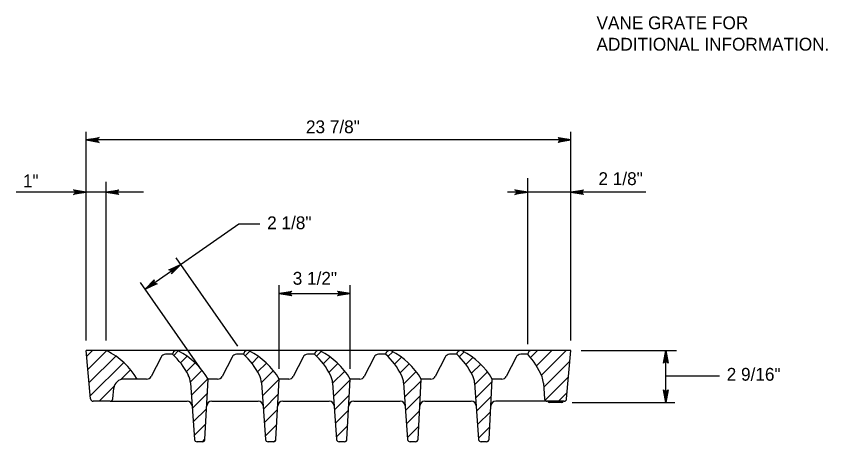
# Model space of a CAD drawing. Extents: x 2087776 to 2104538, y 970919 to 982612.
# Drawn here: x 2097624 to 2098246, y 977730 to 978057 of the extents above; entities that cross this region are included whole.
import ezdxf

# ---------------------------------------------------------------- set-up
doc = ezdxf.new("R2010")
doc.units = 0
doc.layers.add('1', color=7, linetype='Continuous')

msp = doc.modelspace()

# ---------------------------------------------------------------- linework, layer by layer
at = {"layer": '1'}
for p, q in [((2097677.36, 977807.97), (2097677.36, 977967.86)), ((2098048.69, 977807.97), (2098048.69, 977967.86)), ((2098048.69, 977961.64), (2097677.36, 977961.64)), ((2098048.69, 977961.64), (2098048.69, 977961.64)), ((2098015.64, 977805.05), (2098015.64, 977932.25)), ((2097692.61, 977807.97), (2097692.61, 977929.44)), ((2097721.26, 977921.64), (2097623.65, 977921.64)), ((2098106.11, 977921.64), (2098000.05, 977921.64)), ((2098048.69, 977807.97), (2098048.69, 977901.23)), ((2097722.51, 977847.21), (2097794.12, 977897.24)), ((2097794.12, 977897.24), (2097810.3, 977897.24)), ((2097677.36, 977807.97), (2097677.36, 977873.52)), ((2097793.44, 977803.65), (2097746.17, 977871.32)), ((2097749.73, 977866.22), (2097749.73, 977866.22)), ((2097766.22, 977784.64), (2097718.95, 977852.31)), ((2097825.11, 977786.04), (2097825.11, 977850.22)), ((2097879.55, 977786.04), (2097879.55, 977850.22)), ((2097825.11, 977844), (2097825.11, 977844)), ((2097825.11, 977844), (2097879.55, 977844)), ((2097680.6, 977763.08), (2097677.36, 977800.19)), ((2097691.94, 977800.19), (2097677.36, 977800.19)), ((2097677.36, 977800.19), (2097677.36, 977800.19)), ((2097677.36, 977800.19), (2097677.36, 977800.19)), ((2097677.74, 977795.8), (2097682.13, 977800.19)), ((2097678.63, 977785.69), (2097692.95, 977800.01)), ((2097746.37, 977800.19), (2097691.94, 977800.19)), ((2097692.61, 977800.19), (2097692.61, 977800.19)), ((2097744.36, 977796.43), (2097747.77, 977799.84)), ((2097800.81, 977800.19), (2097746.37, 977800.19)), ((2097799.07, 977796.16), (2097802.57, 977799.66)), ((2097855.25, 977800.19), (2097800.81, 977800.19)), ((2097853.79, 977795.88), (2097857.37, 977799.47)), ((2097909.69, 977800.19), (2097855.25, 977800.19)), ((2097908.5, 977795.6), (2097912.17, 977799.28)), ((2097964.12, 977800.19), (2097909.69, 977800.19)), ((2098018.56, 977800.19), (2097964.12, 977800.19)), ((2098017.74, 977794.87), (2098023.07, 977800.19)), ((2098048.69, 977800.19), (2098018.56, 977800.19)), ((2098022.32, 977788.45), (2098034.07, 977800.19)), ((2098026.09, 977781.22), (2098045.06, 977800.19)), ((2098045.45, 977763.08), (2098048.69, 977800.19)), ((2098048.69, 977800.19), (2098048.69, 977800.19)), ((2098048.69, 977800.19), (2098048.69, 977800.19)), ((2098048.69, 977800.19), (2098048.69, 977800.19)), ((2098056.47, 977800.19), (2098129.65, 977800.19)), ((2098121.42, 977760.34), (2098121.42, 977800.19)), ((2097679.51, 977775.57), (2097699.9, 977795.97)), ((2097734.6, 977795.16), (2097727.04, 977780.38)), ((2097743.46, 977797.28), (2097738.06, 977797.28)), ((2097749.58, 977790.65), (2097754.67, 977795.74)), ((2097789.04, 977795.16), (2097781.48, 977780.38)), ((2097797.9, 977797.28), (2097792.5, 977797.28)), ((2097797.9, 977797.28), (2097797.9, 977797.28)), ((2097804.25, 977790.34), (2097809.43, 977795.51)), ((2097843.47, 977795.16), (2097835.92, 977780.38)), ((2097852.33, 977797.28), (2097846.93, 977797.28)), ((2097858.93, 977790.03), (2097864.19, 977795.28)), ((2097897.91, 977795.16), (2097890.35, 977780.38)), ((2097906.77, 977797.28), (2097901.37, 977797.28)), ((2097913.61, 977789.71), (2097918.94, 977795.05)), ((2097952.35, 977795.16), (2097944.79, 977780.38)), ((2097961.21, 977797.28), (2097955.81, 977797.28)), ((2097963.21, 977795.33), (2097966.97, 977799.09)), ((2097968.28, 977789.4), (2097973.7, 977794.82)), ((2098006.78, 977795.16), (2097999.23, 977780.38)), ((2098015.64, 977797.28), (2098010.25, 977797.28)), ((2098015.64, 977797.28), (2098015.64, 977797.28)), ((2097680.39, 977765.46), (2097706.02, 977791.08)), ((2097754.03, 977784.11), (2097760.74, 977790.82)), ((2097808.67, 977783.76), (2097815.46, 977790.55)), ((2097863.31, 977783.41), (2097870.18, 977790.28)), ((2097917.95, 977783.05), (2097924.9, 977790)), ((2097972.58, 977782.7), (2097979.61, 977789.73)), ((2098027.93, 977772.06), (2098047.99, 977792.12)), ((2097703.83, 977777.9), (2097711.34, 977785.4)), ((2097757.14, 977776.22), (2097766.02, 977785.1)), ((2097811.63, 977775.72), (2097820.7, 977784.79)), ((2097866.11, 977775.21), (2097875.38, 977784.48)), ((2097920.58, 977774.69), (2097930.06, 977784.17)), ((2097975.05, 977774.17), (2097984.73, 977783.85)), ((2098121.42, 977780.65), (2098162.66, 977780.65)), ((2097716.24, 977778.26), (2097706.17, 977778.26)), ((2097715.19, 977778.26), (2097715.85, 977778.92)), ((2097723.58, 977778.26), (2097716.24, 977778.26)), ((2097721.2, 977778.26), (2097721.2, 977778.26)), ((2097757.23, 977775.33), (2097760.26, 977732.01)), ((2097757.88, 977765.96), (2097770.49, 977778.58)), ((2097768.25, 977732.04), (2097770.68, 977778.26)), ((2097770.68, 977778.26), (2097770.68, 977778.26)), ((2097770.68, 977778.26), (2097770.68, 977778.26)), ((2097778.02, 977778.26), (2097770.68, 977778.26)), ((2097811.66, 977775.33), (2097814.69, 977732.01)), ((2097812.35, 977765.45), (2097825.11, 977778.2)), ((2097822.69, 977732.04), (2097825.11, 977778.26)), ((2097825.11, 977778.26), (2097825.11, 977778.26)), ((2097832.46, 977778.26), (2097825.11, 977778.26)), ((2097866.1, 977775.33), (2097869.13, 977732.01)), ((2097866.83, 977764.93), (2097879.52, 977777.62)), ((2097877.13, 977732.04), (2097879.55, 977778.26)), ((2097886.89, 977778.26), (2097879.55, 977778.26)), ((2097920.54, 977775.33), (2097923.57, 977732.01)), ((2097921.3, 977764.41), (2097933.92, 977777.04)), ((2097931.57, 977732.04), (2097933.99, 977778.26)), ((2097941.33, 977778.26), (2097933.99, 977778.26)), ((2097974.97, 977775.33), (2097978, 977732.01)), ((2097975.77, 977763.9), (2097988.33, 977776.45)), ((2097986, 977732.04), (2097988.43, 977778.26)), ((2097995.77, 977778.26), (2097988.43, 977778.26)), ((2098027.71, 977775.24), (2098028.56, 977763.12)), ((2098028.95, 977762.08), (2098046.93, 977780.07)), ((2097687.24, 977761.31), (2097698.76, 977772.83)), ((2097697.57, 977763.05), (2097698.44, 977771.3)), ((2097758.6, 977755.68), (2097770.1, 977767.18)), ((2097813.07, 977755.17), (2097824.5, 977766.6)), ((2097867.55, 977754.65), (2097878.91, 977766.01)), ((2097922.02, 977754.13), (2097933.32, 977765.43)), ((2097976.49, 977753.62), (2097987.72, 977764.85)), ((2098039.17, 977761.31), (2098045.88, 977768.01)), ((2097695.64, 977761.31), (2097682.54, 977761.31)), ((2097683.26, 977761.31), (2097683.26, 977761.31)), ((2097694.92, 977761.31), (2097694.92, 977761.31)), ((2097695.64, 977761.31), (2097754.58, 977761.31)), ((2097773.48, 977761.31), (2097809.02, 977761.31)), ((2097827.92, 977761.31), (2097863.45, 977761.31)), ((2097882.35, 977761.31), (2097917.89, 977761.31)), ((2097936.79, 977761.31), (2097972.33, 977761.31)), ((2098030.49, 977761.31), (2097991.23, 977761.31)), ((2098043.51, 977761.31), (2098030.49, 977761.31)), ((2098031.17, 977761.31), (2098031.17, 977761.31)), ((2098041.86, 977760.34), (2098032.14, 977760.34)), ((2098041.86, 977760.34), (2098041.86, 977760.34)), ((2098042.84, 977761.31), (2098042.84, 977761.31)), ((2098049.64, 977760.34), (2098128.42, 977760.34)), ((2098086.61, 977760.34), (2098086.61, 977760.34)), ((2097759.32, 977745.4), (2097769.49, 977755.57)), ((2097813.79, 977744.89), (2097823.89, 977754.99)), ((2097868.26, 977744.37), (2097878.3, 977754.41)), ((2097922.74, 977743.85), (2097932.71, 977753.82)), ((2097977.21, 977743.34), (2097987.11, 977753.24)), ((2097760.04, 977735.12), (2097768.88, 977743.97)), ((2097814.51, 977734.61), (2097823.29, 977743.38)), ((2097868.98, 977734.09), (2097877.69, 977742.8)), ((2097923.46, 977733.57), (2097932.1, 977742.22)), ((2097977.93, 977733.06), (2097986.51, 977741.63)), ((2097766.11, 977730.2), (2097768.27, 977732.36)), ((2097821.14, 977730.24), (2097822.65, 977731.75)), ((2097766.31, 977730.2), (2097762.19, 977730.2)), ((2097820.75, 977730.2), (2097816.63, 977730.2)), ((2097875.19, 977730.2), (2097871.07, 977730.2)), ((2097929.62, 977730.2), (2097925.51, 977730.2)), ((2097984.06, 977730.2), (2097979.94, 977730.2))]:
    msp.add_line(p, q, dxfattribs=at)
for points in [[(2097677.36, 977961.64), (2097687.14, 977963.47), (2097686.76, 977963.21), (2097686.39, 977962.95), (2097686.19, 977962.62), (2097686, 977962.29), (2097685.94, 977961.96), (2097685.89, 977961.64), (2097685.94, 977961.31), (2097686, 977960.98), (2097686.19, 977960.65), (2097686.39, 977960.32), (2097686.76, 977960.06), (2097687.14, 977959.8), (2097677.36, 977961.64), (2097686.76, 977960.06), (2097686.39, 977960.32), (2097677.36, 977961.64), (2097686.19, 977960.65), (2097686, 977960.98), (2097677.36, 977961.64), (2097685.94, 977961.31), (2097685.89, 977961.64), (2097677.36, 977961.64), (2097685.94, 977961.96), (2097686, 977962.29), (2097677.36, 977961.64), (2097686.19, 977962.62), (2097686.39, 977962.95), (2097677.36, 977961.64), (2097686.76, 977963.21)], [(2098048.69, 977961.64), (2098038.91, 977959.8), (2098039.29, 977960.06), (2098039.66, 977960.32), (2098039.86, 977960.65), (2098040.05, 977960.98), (2098040.11, 977961.31), (2098040.16, 977961.64), (2098040.11, 977961.96), (2098040.05, 977962.29), (2098039.86, 977962.62), (2098039.66, 977962.95), (2098039.29, 977963.21), (2098038.91, 977963.47), (2098048.69, 977961.64), (2098039.29, 977963.21), (2098039.66, 977962.95), (2098048.69, 977961.64), (2098039.86, 977962.62), (2098040.05, 977962.29), (2098048.69, 977961.64), (2098040.11, 977961.96), (2098040.16, 977961.64), (2098048.69, 977961.64), (2098040.11, 977961.31), (2098040.05, 977960.98), (2098048.69, 977961.64), (2098039.86, 977960.65), (2098039.66, 977960.32), (2098048.69, 977961.64), (2098039.29, 977960.06)], [(2097677.36, 977921.64), (2097667.57, 977919.8), (2097667.95, 977920.06), (2097668.32, 977920.32), (2097668.52, 977920.65), (2097668.71, 977920.98), (2097668.77, 977921.31), (2097668.83, 977921.64), (2097668.77, 977921.96), (2097668.71, 977922.29), (2097668.52, 977922.62), (2097668.32, 977922.95), (2097667.95, 977923.21), (2097667.57, 977923.47), (2097677.36, 977921.64), (2097667.95, 977923.21), (2097668.32, 977922.95), (2097677.36, 977921.64), (2097668.52, 977922.62), (2097668.71, 977922.29), (2097677.36, 977921.64), (2097668.77, 977921.96), (2097668.83, 977921.64), (2097677.36, 977921.64), (2097668.77, 977921.31), (2097668.71, 977920.98), (2097677.36, 977921.64), (2097668.52, 977920.65), (2097668.32, 977920.32), (2097677.36, 977921.64), (2097667.95, 977920.06)], [(2097692.61, 977921.64), (2097702.4, 977923.47), (2097702.02, 977923.21), (2097701.64, 977922.95), (2097701.45, 977922.62), (2097701.25, 977922.29), (2097701.2, 977921.96), (2097701.14, 977921.64), (2097701.2, 977921.31), (2097701.25, 977920.98), (2097701.45, 977920.65), (2097701.64, 977920.32), (2097702.02, 977920.06), (2097702.4, 977919.8), (2097692.61, 977921.64), (2097702.02, 977920.06), (2097701.64, 977920.32), (2097692.61, 977921.64), (2097701.45, 977920.65), (2097701.25, 977920.98), (2097692.61, 977921.64), (2097701.2, 977921.31), (2097701.14, 977921.64), (2097692.61, 977921.64), (2097701.2, 977921.96), (2097701.25, 977922.29), (2097692.61, 977921.64), (2097701.45, 977922.62), (2097701.64, 977922.95), (2097692.61, 977921.64), (2097702.02, 977923.21)], [(2098015.64, 977921.64), (2098005.86, 977919.8), (2098006.24, 977920.06), (2098006.61, 977920.32), (2098006.81, 977920.65), (2098007, 977920.98), (2098007.06, 977921.31), (2098007.11, 977921.64), (2098007.06, 977921.96), (2098007, 977922.29), (2098006.81, 977922.62), (2098006.61, 977922.95), (2098006.24, 977923.21), (2098005.86, 977923.47), (2098015.64, 977921.64), (2098006.24, 977923.21), (2098006.61, 977922.95), (2098015.64, 977921.64), (2098006.81, 977922.62), (2098007, 977922.29), (2098015.64, 977921.64), (2098007.06, 977921.96), (2098007.11, 977921.64), (2098015.64, 977921.64), (2098007.06, 977921.31), (2098007, 977920.98), (2098015.64, 977921.64), (2098006.81, 977920.65), (2098006.61, 977920.32), (2098015.64, 977921.64), (2098006.24, 977920.06)], [(2098048.69, 977921.64), (2098058.48, 977923.47), (2098058.1, 977923.21), (2098057.73, 977922.95), (2098057.53, 977922.62), (2098057.34, 977922.29), (2098057.28, 977921.96), (2098057.22, 977921.64), (2098057.28, 977921.31), (2098057.34, 977920.98), (2098057.53, 977920.65), (2098057.73, 977920.32), (2098058.1, 977920.06), (2098058.48, 977919.8), (2098048.69, 977921.64), (2098058.1, 977920.06), (2098057.73, 977920.32), (2098048.69, 977921.64), (2098057.53, 977920.65), (2098057.34, 977920.98), (2098048.69, 977921.64), (2098057.28, 977921.31), (2098057.22, 977921.64), (2098048.69, 977921.64), (2098057.28, 977921.96), (2098057.34, 977922.29), (2098048.69, 977921.64), (2098057.53, 977922.62), (2098057.73, 977922.95), (2098048.69, 977921.64), (2098058.1, 977923.21)], [(2097749.73, 977866.22), (2097742.76, 977859.12), (2097742.92, 977859.55), (2097743.08, 977859.98), (2097743.05, 977860.36), (2097743.02, 977860.74), (2097742.88, 977861.04), (2097742.74, 977861.34), (2097742.5, 977861.58), (2097742.27, 977861.81), (2097741.92, 977861.97), (2097741.57, 977862.13), (2097741.12, 977862.13), (2097740.66, 977862.12), (2097749.73, 977866.22), (2097741.12, 977862.13), (2097741.57, 977862.13), (2097749.73, 977866.22), (2097741.92, 977861.97), (2097742.27, 977861.81), (2097749.73, 977866.22), (2097742.5, 977861.58), (2097742.74, 977861.34), (2097749.73, 977866.22), (2097742.88, 977861.04), (2097743.02, 977860.74), (2097749.73, 977866.22), (2097743.05, 977860.36), (2097743.08, 977859.98), (2097749.73, 977866.22), (2097742.92, 977859.55)], [(2097722.51, 977847.21), (2097729.48, 977854.32), (2097729.32, 977853.89), (2097729.16, 977853.46), (2097729.19, 977853.08), (2097729.22, 977852.7), (2097729.36, 977852.4), (2097729.5, 977852.1), (2097729.74, 977851.86), (2097729.97, 977851.62), (2097730.32, 977851.46), (2097730.67, 977851.31), (2097731.13, 977851.31), (2097731.58, 977851.31), (2097722.51, 977847.21), (2097731.13, 977851.31), (2097730.67, 977851.31), (2097722.51, 977847.21), (2097730.32, 977851.46), (2097729.97, 977851.62), (2097722.51, 977847.21), (2097729.74, 977851.86), (2097729.5, 977852.1), (2097722.51, 977847.21), (2097729.36, 977852.4), (2097729.22, 977852.7), (2097722.51, 977847.21), (2097729.19, 977853.08), (2097729.16, 977853.46), (2097722.51, 977847.21), (2097729.32, 977853.89)], [(2097825.11, 977844), (2097834.9, 977845.83), (2097834.52, 977845.57), (2097834.15, 977845.31), (2097833.95, 977844.98), (2097833.76, 977844.66), (2097833.7, 977844.33), (2097833.64, 977844), (2097833.7, 977843.67), (2097833.76, 977843.34), (2097833.95, 977843.02), (2097834.15, 977842.69), (2097834.52, 977842.43), (2097834.9, 977842.16), (2097825.11, 977844), (2097834.52, 977842.43), (2097834.15, 977842.69), (2097825.11, 977844), (2097833.95, 977843.02), (2097833.76, 977843.34), (2097825.11, 977844), (2097833.7, 977843.67), (2097833.64, 977844), (2097825.11, 977844), (2097833.7, 977844.33), (2097833.76, 977844.66), (2097825.11, 977844), (2097833.95, 977844.98), (2097834.15, 977845.31), (2097825.11, 977844), (2097834.52, 977845.57)], [(2097879.55, 977844), (2097869.77, 977842.16), (2097870.14, 977842.43), (2097870.52, 977842.69), (2097870.71, 977843.02), (2097870.91, 977843.34), (2097870.96, 977843.67), (2097871.02, 977844), (2097870.96, 977844.33), (2097870.91, 977844.66), (2097870.71, 977844.98), (2097870.52, 977845.31), (2097870.14, 977845.57), (2097869.77, 977845.83), (2097879.55, 977844), (2097870.14, 977845.57), (2097870.52, 977845.31), (2097879.55, 977844), (2097870.71, 977844.98), (2097870.91, 977844.66), (2097879.55, 977844), (2097870.96, 977844.33), (2097871.02, 977844), (2097879.55, 977844), (2097870.96, 977843.67), (2097870.91, 977843.34), (2097879.55, 977844), (2097870.71, 977843.02), (2097870.52, 977842.69), (2097879.55, 977844), (2097870.14, 977842.43)], [(2098121.42, 977800.19), (2098123.26, 977790.41), (2098123, 977790.78), (2098122.74, 977791.16), (2098122.41, 977791.36), (2098122.08, 977791.55), (2098121.75, 977791.61), (2098121.42, 977791.66), (2098121.1, 977791.61), (2098120.77, 977791.55), (2098120.44, 977791.36), (2098120.11, 977791.16), (2098119.85, 977790.78), (2098119.59, 977790.41), (2098121.42, 977800.19), (2098119.85, 977790.78), (2098120.11, 977791.16), (2098121.42, 977800.19), (2098120.44, 977791.36), (2098120.77, 977791.55), (2098121.42, 977800.19), (2098121.1, 977791.61), (2098121.42, 977791.66), (2098121.42, 977800.19), (2098121.75, 977791.61), (2098122.08, 977791.55), (2098121.42, 977800.19), (2098122.41, 977791.36), (2098122.74, 977791.16), (2098121.42, 977800.19), (2098123, 977790.78)], [(2098121.42, 977760.34), (2098119.59, 977770.12), (2098119.85, 977769.74), (2098120.11, 977769.37), (2098120.44, 977769.17), (2098120.77, 977768.98), (2098121.1, 977768.92), (2098121.42, 977768.87), (2098121.75, 977768.92), (2098122.08, 977768.98), (2098122.41, 977769.17), (2098122.74, 977769.37), (2098123, 977769.74), (2098123.26, 977770.12), (2098121.42, 977760.34), (2098123, 977769.74), (2098122.74, 977769.37), (2098121.42, 977760.34), (2098122.41, 977769.17), (2098122.08, 977768.98), (2098121.42, 977760.34), (2098121.75, 977768.92), (2098121.42, 977768.87), (2098121.42, 977760.34), (2098121.1, 977768.92), (2098120.77, 977768.98), (2098121.42, 977760.34), (2098120.44, 977769.17), (2098120.11, 977769.37), (2098121.42, 977760.34), (2098119.85, 977769.74)]]:
    msp.add_lwpolyline(points, dxfattribs=at)
for centre, radius, start, end in [((2097691.94, 977797.28), 2.92, 63.63032, 90), ((2097669.05, 977751.12), 54.44, 29.91165, 63.63032), ((2097746.37, 977797.28), 2.92, 63.63032, 180), ((2097723.49, 977751.12), 54.44, 29.91165, 63.63032), ((2097800.81, 977797.28), 2.92, 63.63032, 180), ((2097777.93, 977751.12), 54.44, 29.91165, 63.63032), ((2097855.25, 977797.28), 2.92, 63.63032, 180), ((2097832.37, 977751.12), 54.44, 29.91165, 63.63032), ((2097909.69, 977797.28), 2.92, 63.63032, 180), ((2097886.8, 977751.12), 54.44, 29.91165, 63.63032), ((2097964.12, 977797.28), 2.92, 63.63032, 180), ((2097941.24, 977751.12), 54.44, 29.91165, 63.63032), ((2098018.56, 977797.28), 2.92, 90, 180), ((2097738.06, 977793.39), 3.89, 90, 152.92173), ((2097704.36, 977755.05), 57.55, 27.21209, 47.20741), ((2097792.5, 977793.39), 3.89, 90, 152.92173), ((2097758.8, 977755.05), 57.55, 27.21209, 47.20741), ((2097846.93, 977793.39), 3.89, 90, 152.92173), ((2097813.24, 977755.05), 57.55, 27.21209, 47.20741), ((2097901.37, 977793.39), 3.89, 90, 152.92173), ((2097867.67, 977755.05), 57.55, 27.21209, 47.20741), ((2097955.81, 977793.39), 3.89, 90, 152.92173), ((2097922.11, 977755.05), 57.55, 27.21209, 47.20741), ((2098010.25, 977793.39), 3.89, 90, 152.92173), ((2097973.31, 977758.3), 57.55, 22.18189, 42.63349), ((2097741.71, 977774.25), 15.55, 4, 27.21209), ((2097796.15, 977774.25), 15.55, 4, 27.21209), ((2097850.58, 977774.25), 15.55, 4, 27.21209), ((2097905.02, 977774.25), 15.55, 4, 27.21209), ((2097959.46, 977774.25), 15.55, 4, 27.21209), ((2097706.17, 977770.49), 7.78, 90, 174), ((2097723.58, 977782.15), 3.89, 270, 332.92173), ((2097778.02, 977782.15), 3.89, 270, 332.92173), ((2097832.46, 977782.15), 3.89, 270, 332.92173), ((2097886.89, 977782.15), 3.89, 270, 332.92173), ((2097941.33, 977782.15), 3.89, 270, 332.92173), ((2097995.77, 977782.15), 3.89, 270, 332.92173), ((2098012.19, 977774.15), 15.55, 4, 22.18189), ((2097682.54, 977763.25), 1.94, 185, 270), ((2097695.64, 977763.25), 1.94, 270, 354), ((2098030.49, 977763.25), 1.94, 184, 270), ((2098043.51, 977763.25), 1.94, 270, 355), ((2097754.58, 977757.42), 3.89, 4, 90), ((2097773.48, 977757.42), 3.89, 90, 177), ((2097809.02, 977757.42), 3.89, 4, 90), ((2097827.92, 977757.42), 3.89, 90, 177), ((2097863.45, 977757.42), 3.89, 4, 90), ((2097882.35, 977757.42), 3.89, 90, 177), ((2097917.89, 977757.42), 3.89, 4, 90), ((2097936.79, 977757.42), 3.89, 90, 177), ((2097972.33, 977757.42), 3.89, 4, 90), ((2097991.23, 977757.42), 3.89, 90, 177), ((2098032.14, 977761.31), 0.972, 180, 270), ((2098041.86, 977761.31), 0.972, 270, 0), ((2097762.19, 977732.15), 1.94, 184, 270), ((2097766.31, 977732.15), 1.94, 270, 357), ((2097816.63, 977732.15), 1.94, 184, 270), ((2097820.75, 977732.15), 1.94, 270, 357), ((2097871.07, 977732.15), 1.94, 184, 270), ((2097875.19, 977732.15), 1.94, 270, 357), ((2097925.51, 977732.15), 1.94, 184, 270), ((2097929.62, 977732.15), 1.94, 270, 357), ((2097979.94, 977732.15), 1.94, 184, 270), ((2097984.06, 977732.15), 1.94, 270, 357)]:
    msp.add_arc(centre, radius, start, end, dxfattribs=at)

# ---------------------------------------------------------------- texts
for s, height, p in [('VANE GRATE FOR ', 9.8425, (2098068.36, 978046.58)), ('ADDITIONAL INFORMATION.', 9.8425, (2098068.36, 978030.17)), ('23 7/8"', 9.843, (2097845.69, 977966.82)), ('2 1/8"', 9.843, (2098069.84, 977927.08)), ('1"', 9.843, (2097628.75, 977925.34)), ('2 1/8"', 9.843, (2097815.95, 977893.21)), ('3 1/2"', 9.843, (2097835.55, 977850.66)), ('2 9/16"', 9.843, (2098168.14, 977777.03))]:
    msp.add_text(s, height=height, dxfattribs=at).set_placement(p)

doc.saveas('drawing.dxf')
